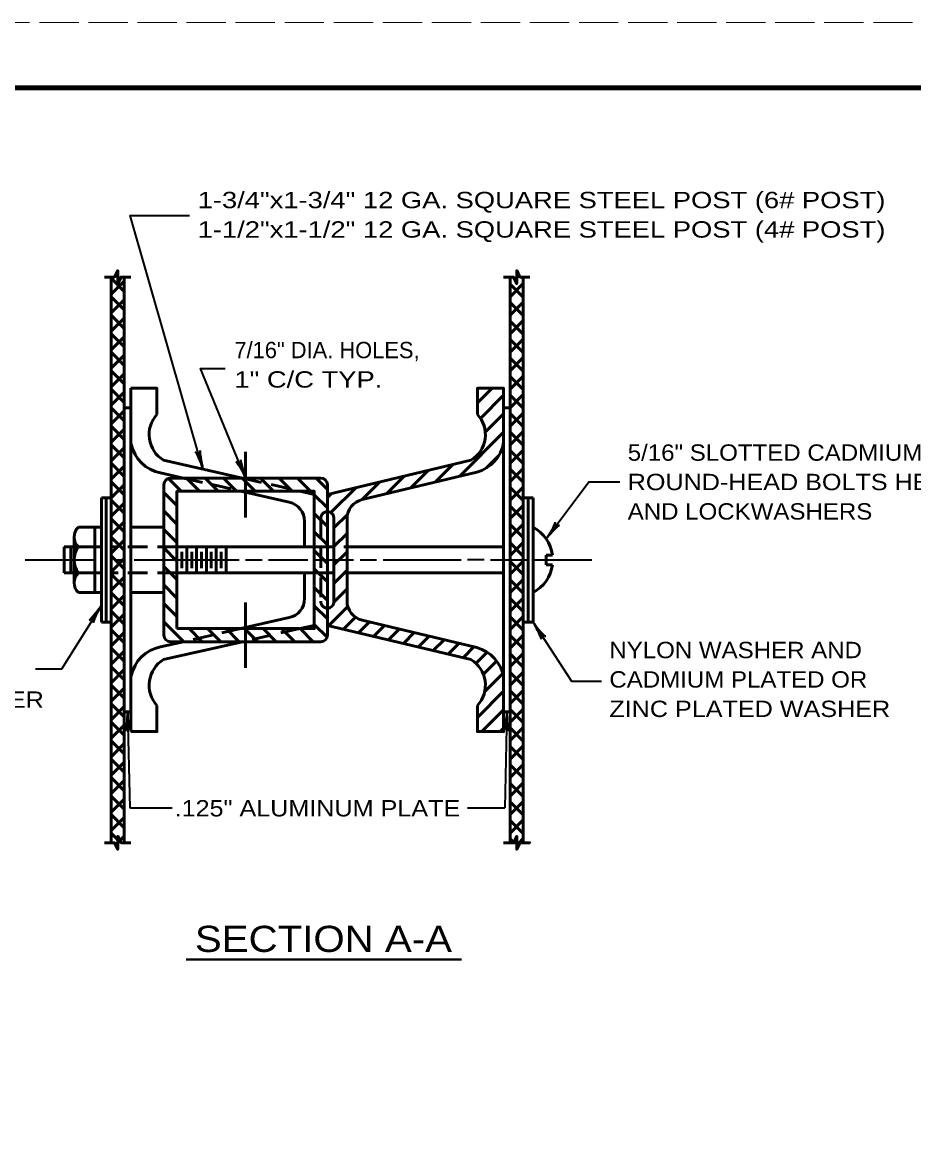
# Model space of a CAD drawing. Extents: x -54 to 626, y -369 to 71.
# Drawn here: x 303.9 to 440.1, y -100.7 to 70.7 of the extents above; entities that cross this region are included whole.
import ezdxf
from ezdxf.enums import TextEntityAlignment as Align

# ---------------------------------------------------------------- set-up
doc = ezdxf.new("R2010")
doc.units = 0
doc.linetypes.add('LONG_DASHED', pattern=[7.5, 6, -1.5])
doc.linetypes.add('MEDIUM_DASHED', pattern=[4.5, 3, -1.5])
doc.layers.add('1', color=7, linetype='Continuous', lineweight=53)
doc.layers.add('61', color=7, linetype='Continuous', lineweight=35)

msp = doc.modelspace()

# ---------------------------------------------------------------- linework, layer by layer
at = {"layer": '1'}
for p, q in [((379.439, 32.606), (379.496, 32.663)), ((316.439, 31.776), (317.439, 31.776)), ((319.439, 29.592), (317.439, 31.592)), ((317.439, 29.145), (319.439, 31.145)), ((319.439, 31.776), (320.439, 31.776)), ((378.439, 31.776), (377.439, 31.776)), ((378.439, 31.606), (378.609, 31.776)), ((379.675, 32.305), (379.439, 32.541)), ((380.439, 31.541), (380.204, 31.776)), ((381.439, 31.776), (380.439, 31.776)), ((378.439, 28.778), (380.439, 30.778)), ((380.439, 28.712), (378.439, 30.712)), ((319.439, 26.763), (317.439, 28.763)), ((317.439, 26.316), (319.439, 28.316)), ((378.439, 25.949), (380.439, 27.949)), ((380.439, 25.884), (378.439, 27.884)), ((319.439, 23.935), (317.439, 25.935)), ((317.439, 23.488), (319.439, 25.488)), ((378.439, 23.121), (380.439, 25.121)), ((380.439, 23.055), (378.439, 25.055)), ((319.439, 21.107), (317.439, 23.107)), ((317.439, 20.659), (319.439, 22.659)), ((378.439, 20.292), (380.439, 22.292)), ((380.439, 20.227), (378.439, 22.227)), ((319.439, 18.278), (317.439, 20.278)), ((317.439, 17.831), (319.439, 19.831)), ((378.439, 17.464), (380.439, 19.464)), ((380.439, 17.398), (378.439, 19.398)), ((319.439, 15.45), (317.439, 17.45)), ((317.439, 15.002), (319.439, 17.002)), ((378.439, 14.636), (380.439, 16.636)), ((380.439, 14.57), (378.439, 16.57)), ((319.439, 12.621), (317.439, 14.621)), ((317.439, 12.174), (319.439, 14.174)), ((320.439, 14.776), (320.439, -37.724)), ((373.439, 12.533), (375.683, 14.776)), ((378.439, 11.807), (380.439, 13.807)), ((380.439, 11.742), (378.439, 13.742)), ((373.904, 10.169), (377.439, 13.705)), ((319.439, 9.793), (317.439, 11.793)), ((317.439, 9.346), (319.439, 11.346)), ((319.439, 11.776), (320.439, 11.776)), ((374.615, 8.052), (377.439, 10.876)), ((378.439, 11.776), (377.439, 11.776)), ((378.439, 8.979), (380.439, 10.979)), ((380.439, 8.913), (378.439, 10.913)), ((319.439, 6.965), (317.439, 8.964)), ((317.439, 6.517), (319.439, 8.517)), ((370.695, 1.303), (377.439, 8.048)), ((378.439, 6.15), (380.439, 8.15)), ((380.439, 6.085), (378.439, 8.085)), ((319.439, 4.136), (317.439, 6.136)), ((317.439, 3.689), (319.439, 5.689)), ((377.439, 6.478), (377.439, -29.425)), ((378.439, 3.322), (380.439, 5.322)), ((380.439, 3.256), (378.439, 5.256)), ((325.439, 3.776), (337.496, 1.036)), ((337.996, 5.036), (337.996, -4.964)), ((374.843, 2.623), (376.611, 4.391)), ((319.439, 1.308), (317.439, 3.308)), ((317.439, 0.86), (319.439, 2.86)), ((324.996, 1.826), (328.472, 1.036)), ((355.799, -2.254), (373.339, 1.935)), ((363.264, -0.471), (365.965, 2.23)), ((366.979, 0.416), (369.681, 3.117)), ((378.439, 0.493), (380.439, 2.494)), ((380.439, 0.428), (378.439, 2.428)), ((319.439, -1.521), (317.439, 0.479)), ((317.439, -1.968), (319.439, 0.032)), ((325.496, -22.984), (325.496, 0.036)), ((328.128, -0.964), (326.186, 0.978)), ((326.496, 1.036), (349.496, 1.036)), ((330.957, -0.964), (328.957, 1.036)), ((333.785, -0.964), (331.785, 1.036)), ((336.613, -0.964), (334.613, 1.036)), ((339.442, -0.964), (337.442, 1.036)), ((342.27, -0.964), (340.27, 1.036)), ((345.099, -0.964), (343.099, 1.036)), ((347.927, -0.964), (345.927, 1.036)), ((350.496, -0.704), (348.756, 1.036)), ((350.496, 0.036), (350.496, -1.464)), ((355.832, -2.246), (358.533, 0.455)), ((359.548, -1.359), (362.249, 1.343)), ((327.496, -3.16), (325.496, -1.16)), ((337.272, -0.964), (344.661, -2.643)), ((346.296, -0.964), (348.496, -1.464)), ((350.496, -3.533), (348.496, -1.533)), ((350.496, -1.925), (351.102, -1.319)), ((351.001, -4.248), (354.818, -0.432)), ((378.439, -2.335), (380.439, -0.335)), ((380.439, -2.401), (378.439, -0.4)), ((315.939, -1.974), (315.939, -20.974)), ((315.939, -1.974), (317.439, -1.974)), ((316.689, -1.974), (316.689, -20.974)), ((319.439, -4.349), (317.439, -2.349)), ((317.439, -4.797), (319.439, -2.797)), ((378.439, -5.163), (380.439, -3.163)), ((380.439, -5.229), (378.439, -3.229)), ((381.939, -1.974), (380.439, -1.974)), ((381.189, -1.974), (381.189, -20.974)), ((381.939, -1.974), (381.939, -20.974)), ((327.496, -5.989), (325.496, -3.989)), ((350.496, -6.361), (348.496, -4.361)), ((350.496, -4.089), (350.496, -18.859)), ((351.496, -6.582), (353.574, -4.504)), ((315.939, -6.474), (312.439, -6.474)), ((314.939, -6.474), (314.939, -16.474)), ((319.439, -7.178), (317.439, -5.178)), ((317.439, -7.625), (319.439, -5.625)), ((325.496, -6.474), (320.439, -6.474)), ((327.496, -8.817), (325.496, -6.817)), ((346.996, -5.569), (346.996, -9.474)), ((351.496, -5.172), (351.496, -17.776)), ((353.496, -17.776), (353.496, -5.172)), ((378.439, -7.992), (380.439, -5.992)), ((380.439, -8.057), (378.439, -6.057)), ((311.767, -7.979), (311.767, -14.968)), ((319.439, -10.006), (317.439, -8.006)), ((317.439, -10.453), (319.439, -8.453)), ((350.496, -9.19), (348.496, -7.19)), ((351.496, -9.41), (353.496, -7.41)), ((315.939, -9.474), (310.267, -9.474)), ((310.267, -9.474), (310.267, -13.474)), ((311.267, -9.474), (311.267, -13.474)), ((327.496, -11.646), (325.496, -9.646)), ((327.496, -9.474), (348.496, -9.474)), ((328.246, -10.224), (328.246, -12.724)), ((328.996, -9.474), (328.996, -13.474)), ((329.746, -10.224), (329.746, -12.724)), ((330.496, -9.474), (330.496, -13.474)), ((331.246, -10.224), (331.246, -12.724)), ((331.996, -9.474), (331.996, -13.474)), ((332.746, -10.224), (332.746, -12.724)), ((333.496, -9.474), (333.496, -13.474)), ((334.246, -10.224), (334.246, -12.724)), ((334.996, -9.474), (334.996, -13.474)), ((350.496, -12.018), (348.496, -10.018)), ((351.496, -12.239), (353.496, -10.239)), ((353.496, -9.474), (377.439, -9.474)), ((378.439, -10.82), (380.439, -8.82)), ((380.439, -10.886), (378.439, -8.886)), ((319.439, -12.835), (317.439, -10.835)), ((317.439, -13.282), (319.439, -11.282)), ((378.439, -13.649), (380.439, -11.649)), ((380.439, -13.714), (378.439, -11.714)), ((383.939, -10.724), (383.939, -12.224)), ((383.939, -10.724), (384.89, -10.724)), ((315.939, -13.474), (310.267, -13.474)), ((319.439, -15.663), (317.439, -13.663)), ((327.496, -14.474), (325.496, -12.474)), ((327.496, -13.474), (348.496, -13.474)), ((346.996, -13.474), (346.996, -17.379)), ((350.496, -14.847), (348.496, -12.847)), ((351.496, -15.067), (353.496, -13.067)), ((353.496, -13.474), (377.439, -13.474)), ((383.939, -12.224), (384.89, -12.224)), ((317.439, -16.11), (319.439, -14.11)), ((327.496, -17.302), (325.496, -15.302)), ((378.439, -16.477), (380.439, -14.477)), ((380.439, -16.543), (378.439, -14.543)), ((315.939, -16.474), (312.439, -16.474)), ((319.439, -18.491), (317.439, -16.491)), ((317.439, -18.939), (319.439, -16.939)), ((325.496, -16.474), (320.439, -16.474)), ((350.496, -17.675), (348.496, -15.675)), ((351.478, -17.913), (353.496, -15.896)), ((327.496, -20.131), (325.496, -18.131)), ((337.996, -17.984), (337.996, -27.984)), ((350.496, -20.503), (348.496, -18.503)), ((350.496, -18.895), (350.534, -18.858)), ((350.69, -21.53), (353.629, -18.591)), ((378.439, -19.305), (380.439, -17.305)), ((380.439, -19.371), (378.439, -17.371)), ((319.439, -21.32), (317.439, -19.32)), ((317.439, -21.767), (319.439, -19.767)), ((337.272, -21.984), (344.661, -20.304)), ((352.973, -22.075), (354.813, -20.236)), ((378.439, -22.134), (380.439, -20.134)), ((380.439, -22.2), (378.439, -20.2)), ((315.939, -20.974), (317.439, -20.974)), ((319.439, -24.148), (317.439, -22.148)), ((328.52, -23.984), (325.496, -20.959)), ((331.349, -23.984), (329.349, -21.984)), ((334.177, -23.984), (332.177, -21.984)), ((337.006, -23.984), (335.006, -21.984)), ((339.834, -23.984), (337.834, -21.984)), ((342.663, -23.984), (340.663, -21.984)), ((345.491, -23.984), (343.491, -21.984)), ((346.296, -21.984), (348.496, -21.484)), ((348.32, -23.984), (346.32, -21.984)), ((350.437, -23.273), (348.496, -21.332)), ((350.496, -21.484), (350.496, -22.984)), ((355.257, -22.62), (356.916, -20.96)), ((373.339, -24.882), (355.799, -20.694)), ((357.54, -23.166), (359.2, -21.506)), ((359.823, -23.711), (361.483, -22.051)), ((381.939, -20.974), (380.439, -20.974)), ((317.439, -24.596), (319.439, -22.596)), ((324.996, -24.773), (328.472, -23.984)), ((325.439, -26.724), (337.496, -23.984)), ((349.496, -23.984), (326.496, -23.984)), ((362.106, -24.256), (363.766, -22.596)), ((364.389, -24.801), (366.049, -23.142)), ((366.673, -25.347), (368.332, -23.687)), ((378.439, -24.962), (380.439, -22.962)), ((380.439, -25.028), (378.439, -23.028)), ((319.439, -26.977), (317.439, -24.977)), ((317.439, -27.424), (319.439, -25.424)), ((368.956, -25.892), (370.616, -24.232)), ((371.239, -26.437), (372.899, -24.777)), ((373.198, -27.306), (374.906, -25.599)), ((374.329, -29.004), (376.364, -26.969)), ((378.439, -27.791), (380.439, -25.791)), ((380.439, -27.856), (378.439, -25.856)), ((319.439, -29.805), (317.439, -27.805)), ((317.439, -30.252), (319.439, -28.252)), ((374.519, -31.642), (377.293, -28.868)), ((378.439, -30.619), (380.439, -28.619)), ((380.439, -30.685), (378.439, -28.685)), ((319.439, -32.633), (317.439, -30.633)), ((317.439, -33.081), (319.439, -31.081)), ((373.439, -35.55), (377.439, -31.55)), ((378.439, -33.448), (380.439, -31.448)), ((380.439, -33.513), (378.439, -31.513)), ((319.439, -35.462), (317.439, -33.462)), ((317.439, -35.909), (319.439, -33.909)), ((378.439, -36.276), (380.439, -34.276)), ((319.439, -34.724), (320.439, -34.724)), ((374.094, -37.724), (377.439, -34.379)), ((378.439, -34.724), (377.439, -34.724)), ((380.439, -36.342), (378.439, -34.342)), ((319.439, -38.29), (317.439, -36.29)), ((317.439, -38.738), (319.439, -36.738)), ((376.923, -37.724), (377.439, -37.207)), ((378.439, -39.105), (380.439, -37.105)), ((380.439, -39.17), (378.439, -37.17)), ((319.439, -41.119), (317.439, -39.119)), ((317.439, -41.566), (319.439, -39.566)), ((378.439, -41.933), (380.439, -39.933)), ((380.439, -41.998), (378.439, -39.998)), ((319.439, -43.947), (317.439, -41.947)), ((317.439, -44.395), (319.439, -42.395)), ((378.439, -44.761), (380.439, -42.761)), ((380.439, -44.827), (378.439, -42.827)), ((319.439, -46.776), (317.439, -44.776)), ((317.439, -47.223), (319.439, -45.223)), ((378.439, -47.59), (380.439, -45.59)), ((380.439, -47.655), (378.439, -45.655)), ((319.439, -49.604), (317.439, -47.604)), ((317.439, -50.051), (319.439, -48.051)), ((378.439, -50.418), (380.439, -48.418)), ((380.439, -50.484), (378.439, -48.484)), ((319.439, -52.432), (317.439, -50.432)), ((317.439, -52.88), (319.439, -50.88)), ((378.439, -53.247), (380.439, -51.247)), ((380.439, -53.312), (378.439, -51.312)), ((316.439, -54.724), (317.439, -54.724)), ((318.439, -54.261), (317.439, -53.261)), ((318.101, -55.047), (318.439, -54.708)), ((318.768, -54.38), (319.439, -53.708)), ((319.439, -54.724), (320.439, -54.724)), ((378.439, -54.724), (377.439, -54.724)), ((379.022, -54.724), (378.439, -54.141)), ((379.791, -54.724), (380.439, -54.075))]:
    msp.add_line(p, q, dxfattribs=at)
at = {"layer": '1', "linetype": 'MEDIUM_DASHED'}
for p, q in [((328.472, 1.036), (337.272, -0.964)), ((337.496, 1.036), (346.296, -0.964)), ((349.496, -5.172), (349.496, -17.776)), ((327.496, -9.474), (317.439, -9.474)), ((348.496, -9.474), (353.496, -9.474)), ((327.496, -13.474), (317.439, -13.474)), ((348.496, -13.474), (353.496, -13.474)), ((337.272, -21.984), (328.472, -23.984)), ((346.296, -21.984), (337.496, -23.984))]:
    msp.add_line(p, q, dxfattribs=at)
at = {"layer": '1', "lineweight": 35}
for p, q in [((304.267, -11.474), (314.939, -11.474)), ((317.939, -11.474), (318.939, -11.474)), ((320.939, -11.474), (336.996, -11.474)), ((337.996, -11.474), (340.496, -11.474)), ((341.496, -11.474), (347.496, -11.474)), ((348.496, -11.474), (354.496, -11.474)), ((355.496, -11.474), (357.996, -11.474)), ((358.996, -11.474), (370.939, -11.474)), ((374.439, -11.474), (371.939, -11.474)), ((375.439, -11.474), (381.189, -11.474)), ((381.939, -11.474), (390.939, -11.474)), ((319.939, -34.724), (320.264, -49.368)), ((377.939, -34.724), (377.615, -49.368)), ((320.264, -49.368), (326.74, -49.368)), ((371.901, -49.368), (377.615, -49.368))]:
    msp.add_line(p, q, dxfattribs=at)
at = {"layer": '1', "lineweight": 40}
msp.add_line((328.909, -72.599), (370.977, -72.599), dxfattribs=at)
at = {"layer": '1', "lineweight": 35}
for points in [[(331.468, 2.406), (320.351, 41.223), (329.416, 41.223)], [(337.996, 1.036), (331.095, 17.796), (334.856, 17.796)], [(383.928, -8.242), (390.445, 0.47), (395.195, 0.47)], [(315.939, -18.439), (309.824, -28.172), (305.865, -28.172)], [(381.939, -20.974), (387.806, -30.02), (392.424, -30.02)]]:
    msp.add_lwpolyline(points, dxfattribs=at)
at = {"layer": '1'}
for points in [[(317.439, -54.724), (317.439, 31.776), (317.939, 31.776), (318.439, 32.776), (318.439, 30.776), (318.939, 31.776), (319.439, 31.776), (319.439, -54.724), (318.939, -54.724), (318.439, -53.724), (318.439, -55.724), (317.939, -54.724)], [(378.439, -54.724), (378.439, 31.776), (378.939, 31.776), (379.439, 30.776), (379.439, 32.776), (379.939, 31.776), (380.439, 31.776), (380.439, -54.724), (381.439, -54.724)], [(378.439, -54.724), (378.439, 31.776), (378.939, 31.776), (379.439, 30.776), (379.439, 32.776), (379.939, 31.776), (380.439, 31.776), (380.439, -54.724), (379.939, -54.724), (379.439, -55.724), (379.439, -53.724), (378.939, -54.724)], [(327.496, -21.984), (327.496, -0.964), (348.496, -0.964), (348.496, -21.984)]]:
    msp.add_lwpolyline(points, close=True, dxfattribs=at)
for points in [[(320.439, 14.776), (324.439, 14.776), (324.439, 10.776)], [(377.439, 6.478), (377.439, 14.776), (373.439, 14.776), (373.439, 10.776)], [(372.439, 3.776), (350.496, -1.464), (350.496, -4.089)], [(350.496, -18.859), (350.496, -21.484), (372.439, -26.724)], [(373.439, -33.724), (373.439, -37.724), (377.439, -37.724), (377.439, -29.425)], [(320.439, -37.724), (324.439, -37.724), (324.439, -33.724)]]:
    msp.add_lwpolyline(points, dxfattribs=at)
for centre, radius, start, end in [((327.785, 7.683), 4.557, 137.24693, 239.01328), ((370.093, 7.683), 4.557, 300.98672, 42.75307), ((326.101, 7.466), 5.747, 192.24961, 258.91782), ((371.778, 7.466), 5.747, 285.76159, 350.09896), ((326.496, 0.036), 1, 90, 180), ((349.496, 0.036), 1, 0, 90), ((343.996, -5.569), 3, 0, 77.19552), ((356.496, -5.172), 3, 103.43049, 180), ((350.488, -5.1), 1.011, 355.93658, 88.42125), ((313.775, -7.974), 2.008, 131.68177, 180.15453), ((379.273, -11.474), 5.667, 7.60558, 61.92751), ((313.775, -7.974), 2.008, 180.15453, 228.31823), ((313.775, -7.985), 2.008, 179.84547, 228.31823), ((315.076, -11.474), 3.309, 142.81241, 217.18759), ((315.076, -11.474), 3.309, 142.81241, 217.18759), ((313.775, -14.963), 2.008, 131.68177, 180.15453), ((313.775, -14.974), 2.008, 131.68177, 179.84548), ((379.273, -11.474), 5.667, 298.07249, 352.39442), ((313.775, -14.974), 2.008, 179.84547, 228.31823), ((343.996, -17.379), 3, 282.80434, 0), ((350.488, -17.847), 1.011, 271.57875, 4.06342), ((356.496, -17.776), 3, 180, 256.56931), ((326.496, -22.984), 1, 180, 270), ((349.496, -22.984), 1, 270, 0), ((326.101, -30.413), 5.747, 101.08218, 167.75039), ((371.778, -30.413), 5.747, 9.90104, 74.23791), ((327.785, -30.63), 4.557, 120.98672, 222.75307), ((370.093, -30.63), 4.557, 317.24693, 59.01328)]:
    msp.add_arc(centre, radius, start, end, dxfattribs=at)
at = {"layer": '1', "linetype": 'MEDIUM_DASHED'}
for centre, start, end in [((350.505, -5.1), 91.57875, 184.06342), ((350.505, -17.847), 175.93658, 268.42125)]:
    msp.add_arc(centre, 1.011, start, end, dxfattribs=at)
at = {"layer": '1', "lineweight": 40}
for centre, major_axis, ratio, start_param, end_param in [((331.363, 3.542), (0.315, -1.737), 0.07063, 3.1407148, 5.41811), ((330.902, 3.379), (0.642, -1.674), 0.122415, 0.8963533, 3.1415927), ((337.325, 1.94), (0.824, -1.592), 0.122415, 0.8963533, 3.1415927), ((337.765, 2.153), (0.506, -1.691), 0.07063, 3.1407148, 5.41811), ((384.36, -7.203), (-0.945, -1.523), 0.122415, 0.8963533, 3.1415927), ((384.36, -7.203), (-0.945, -1.523), 0.122415, 0.8963533, 3.1415927), ((384.768, -7.472), (-1.193, -1.301), 0.07063, 3.1407148, 5.41811), ((384.768, -7.472), (-1.193, -1.301), 0.07063, 3.1407148, 5.41811), ((315.164, -19.275), (1.083, 1.394), 0.07063, 3.1407148, 5.41811), ((315.593, -19.51), (0.818, 1.595), 0.122415, 0.8963533, 3.1415927), ((382.372, -22.029), (-0.808, 1.569), 0.07063, 3.1407148, 5.41811), ((382.765, -21.739), (-1.103, 1.413), 0.122415, 0.8963533, 3.1415927), ((319.753, -35.849), (0.137, 1.76), 0.07063, 3.1407148, 5.41811), ((320.24, -35.809), (-0.196, 1.782), 0.122415, 0.8963533, 3.1415927), ((377.703, -35.839), (0.215, 1.752), 0.07063, 3.1407148, 5.41811), ((378.191, -35.821), (-0.117, 1.789), 0.122415, 0.8963533, 3.1415927)]:
    msp.add_ellipse(centre, major_axis=major_axis, ratio=ratio, start_param=start_param, end_param=end_param, dxfattribs=at)
at = {"layer": '61', "linetype": 'LONG_DASHED', "lineweight": 13}
msp.add_line((-53.532, 70.729), (626.488, 70.729), dxfattribs=at)
at = {"layer": '61', "lineweight": 158}
msp.add_lwpolyline([(615.508, 60.729), (-23.532, 60.729), (-23.532, -359.291)], dxfattribs=at)

# ---------------------------------------------------------------- texts
at = {"layer": '1'}
for s, width, p in [('1-3/4"x1-3/4" 12 GA. SQUARE STEEL POST (6# POST)', 1.25, (330.659, 42.316)), ('1-1/2"x1-1/2" 12 GA. SQUARE STEEL POST (4# POST)', 1.25, (330.659, 37.816)), ('1" C/C TYP.', 1.25, (336.275, 14.877)), ('5/16" SLOTTED CADMIUM PLATED', 1.1, (396.411, 3.694)), ('ROUND-HEAD BOLTS HEX. NUTS', 1.15, (396.411, -0.805)), ('AND LOCKWASHERS', 1.1, (396.411, -5.305)), ('NYLON WASHER AND', 1.1, (393.604, -26.501)), ('CADMIUM PLATED OR', 1.1, (393.604, -31.001)), ('ZINC PLATED WASHER', 1.15, (264.205, -34.096)), ('ZINC PLATED WASHER', 1.15, (393.604, -35.501))]:
    msp.add_text(s, height=2.5, dxfattribs=dict(at, width=width)).set_placement(p)
msp.add_text('7/16" DIA. HOLES,', height=2.5, dxfattribs=at).set_placement((336.275, 19.377))
at = {"layer": '1', "width": 1.15}
for s, height, p in [('.125" ALUMINUM PLATE', 2.5, (348.969, -50.706)), ('SECTION A-A', 4, (349.891, -71.43))]:
    msp.add_text(s, height=height, dxfattribs=at).set_placement(p, align=Align.CENTER)

doc.saveas('drawing.dxf')
